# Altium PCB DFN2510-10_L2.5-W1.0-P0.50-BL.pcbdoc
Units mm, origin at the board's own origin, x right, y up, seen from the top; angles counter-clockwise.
Board outline 15.35 x 14.58 mm, 2 copper layers (Top Layer, Bottom Layer), stack 0 mm thick; 1 components, 0 nets, 10 pads, 0 vias.
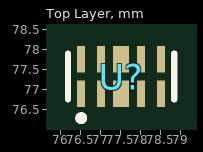
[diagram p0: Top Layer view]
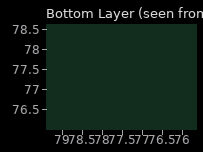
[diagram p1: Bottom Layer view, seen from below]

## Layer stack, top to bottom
Top Layer: signal copper (thickness not stored)
Bottom Layer: signal copper (thickness not stored)

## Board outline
85.202,69.85 69.85,69.85 69.85,84.43 85.202,84.43

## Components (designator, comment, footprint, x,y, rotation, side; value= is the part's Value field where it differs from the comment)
U? "" DFN2510-10_L2.5-W1.0-P0.50-BL 77.526,77.315 r0 top

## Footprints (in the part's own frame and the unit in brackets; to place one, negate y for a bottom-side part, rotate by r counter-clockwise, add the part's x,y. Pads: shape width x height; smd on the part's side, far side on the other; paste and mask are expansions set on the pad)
DFN2510-10_L2.5-W1.0-P0.50-BL [mm]
  rect 0.2x0.665 smd paste-100 mask+0.051: 1(-1,-0.433) 2(-0.5,-0.433) 4(0.5,-0.433) 5(1,-0.433) 6(1,0.433) 7(0.5,0.433) 9(-0.5,0.433) 10(-1,0.433)
  rect 0.4x0.665 smd paste-100 mask+0.051: 3(0,-0.433) 8(0,0.433)
  silkscreen extent -1.33,-1.11 1.33,0.58

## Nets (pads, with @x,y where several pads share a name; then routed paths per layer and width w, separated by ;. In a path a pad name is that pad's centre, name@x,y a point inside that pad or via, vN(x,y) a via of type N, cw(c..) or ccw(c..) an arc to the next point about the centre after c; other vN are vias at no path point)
pads on no net: U?.1 U?.2 U?.3 U?.4 U?.5 U?.6 U?.7 U?.8 U?.9 U?.10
